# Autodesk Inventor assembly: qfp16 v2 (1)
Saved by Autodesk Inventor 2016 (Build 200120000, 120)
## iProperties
Created: 2016-09
Part Number: qfp16 v2 (1)
Document SubType Name: Assembly
Designer: Administrator
Author: Administrator
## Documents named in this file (3)
- c:\worker\convert-fusion-aug-2016\tmp\job-1\13\output\files\2055b865-881d-4af8-ae30-e7b46ec3c804\qfp16 v2 (1).iam
- c:\worker\convert-fusion-aug-2016\tmp\job-1\13\output\files\2055b865-881d-4af8-ae30-e7b46ec3c804\package.ipt
- c:\worker\convert-fusion-aug-2016\tmp\job-1\13\output\files\2055b865-881d-4af8-ae30-e7b46ec3c804\lead (1).ipt
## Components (2 placed, 2 different names)
1. package:1
2. lead (1):1
